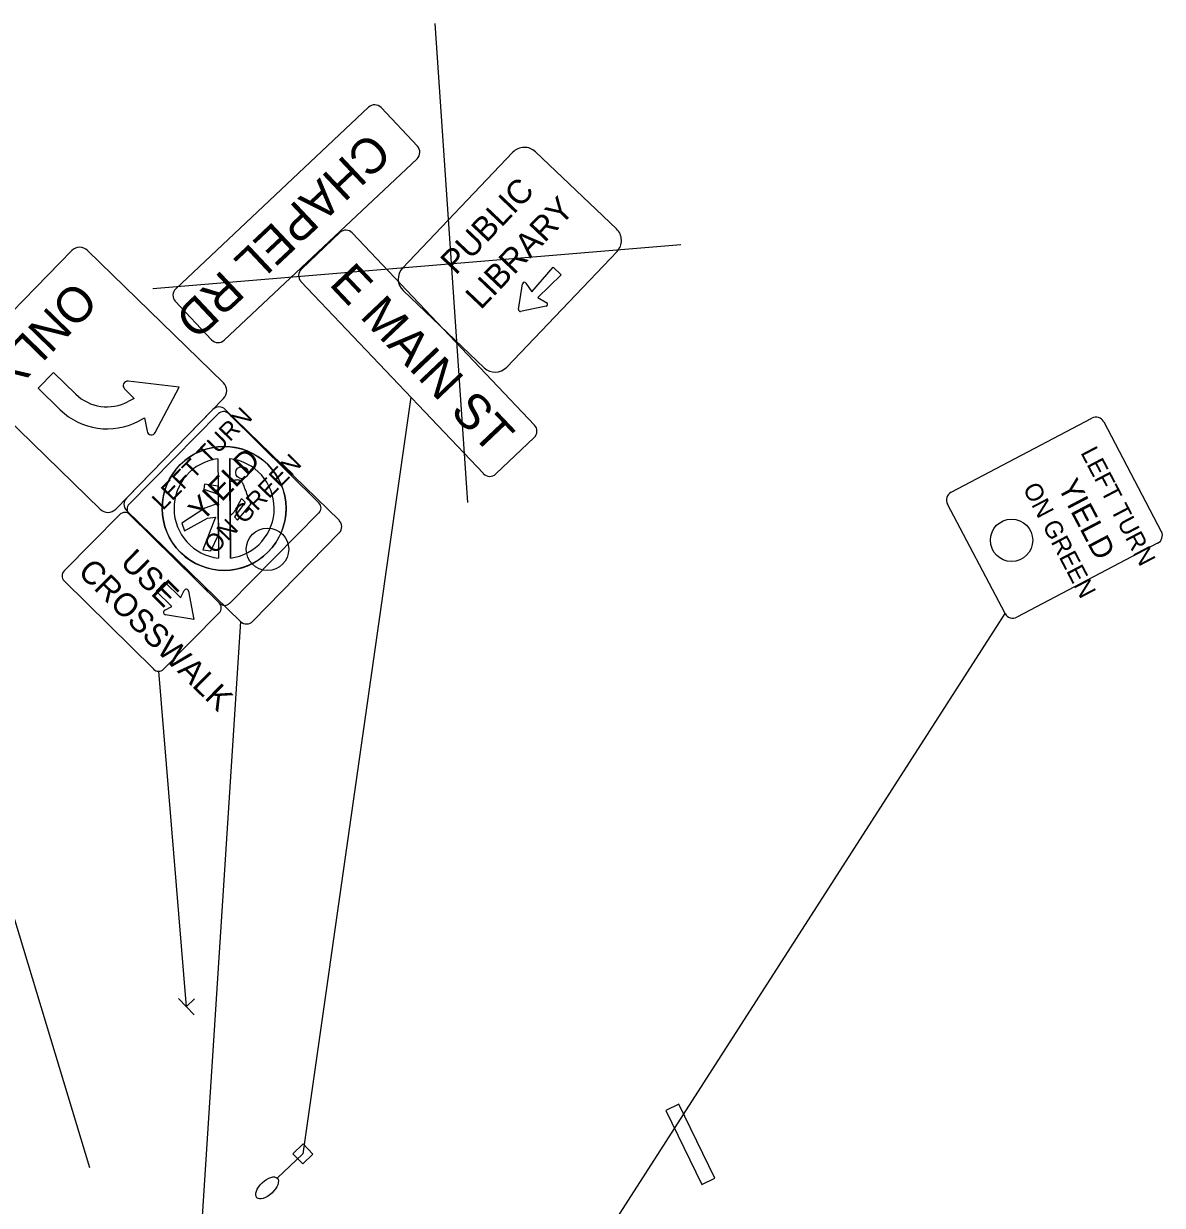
# Model space of a CAD drawing. Extents: x 1479394 to 1483660, y 379804 to 384342.
# Drawn here: x 1479604.6 to 1479765.8, y 379942.2 to 380109.6 of the extents above; entities that cross this region are included whole.
import ezdxf

# ---------------------------------------------------------------- set-up
doc = ezdxf.new("R2010")
doc.units = 0
for name, color, linetype in [('LT_X_Luminaires', 7, 'Continuous'), ('PM_P_Stop_Line', 7, 'Continuous'), ('RD_P_Text', 7, 'Continuous'), ('SC_Scratch15', 7, 'Continuous'), ('SH_Text', 7, 'Continuous')]:
    doc.layers.add(name, color=color, linetype=linetype)

msp = doc.modelspace()

# ---------------------------------------------------------------- linework, layer by layer
at = {"layer": 'LT_X_Luminaires'}
msp.add_line((1479644.13, 379949.51), (1479640.5, 379946.07), dxfattribs=at)
msp.add_lwpolyline([(1479645.54, 379949.47), (1479644.09, 379948.1), (1479642.72, 379949.55), (1479644.17, 379950.93)], close=True, dxfattribs=at)
msp.add_ellipse((1479639.05, 379944.7), major_axis=(-1.45, -1.38), ratio=0.5, dxfattribs=at)
at = {"layer": 'PM_P_Stop_Line'}
msp.add_lwpolyline([(1479697.34, 379956.57), (1479695.49, 379955.68), (1479700.59, 379945.17), (1479702.44, 379946.07)], close=True, dxfattribs=at)
at = {"layer": 'RD_P_Text'}
for p, q in [((1479662.8, 380109.55), (1479667.44, 380041.75)), ((1479697.63, 380078.23), (1479622.88, 380072.01)), ((1479633.77, 380047.96), (1479633.85, 380033.88)), ((1479630.2, 380044.34), (1479630.08, 380043.64)), ((1479630.2, 380044.34), (1479630.08, 380043.64)), ((1479632.11, 380044.08), (1479630.2, 380044.34)), ((1479632.11, 380044.08), (1479630.2, 380044.34)), ((1479633.79, 380044.65), (1479633.79, 380044.5)), ((1479633.79, 380044.5), (1479633.82, 380039.94)), ((1479630.08, 380043.64), (1479632.12, 380042.91)), ((1479630.08, 380043.64), (1479632.12, 380042.91)), ((1479632.12, 380042.91), (1479632.12, 380043.14)), ((1479635.44, 380042.34), (1479635.94, 380041.8)), ((1479635.44, 380042.34), (1479635.94, 380041.8)), ((1479630.25, 380040.94), (1479627, 380038.84)), ((1479630.25, 380040.94), (1479627, 380038.84)), ((1479631.58, 380041.43), (1479630.25, 380040.94)), ((1479631.58, 380041.43), (1479630.25, 380040.94)), ((1479632.13, 380041.61), (1479631.58, 380041.43)), ((1479632.13, 380041.61), (1479631.58, 380041.43)), ((1479632.13, 380041.52), (1479632.13, 380041.61)), ((1479632.16, 380037.16), (1479632.13, 380041.52)), ((1479635.94, 380041.8), (1479634.42, 380039.74)), ((1479635.94, 380041.8), (1479634.42, 380039.74)), ((1479634.84, 380039.26), (1479636.78, 380041.54)), ((1479634.84, 380039.26), (1479636.78, 380041.54)), ((1479636.78, 380041.54), (1479636.77, 380041.56)), ((1479636.78, 380041.54), (1479636.77, 380041.56)), ((1479627.37, 380037.75), (1479630.6, 380039.53)), ((1479627.37, 380037.75), (1479630.6, 380039.53)), ((1479631.74, 380039.67), (1479629.97, 380035.07)), ((1479631.74, 380039.67), (1479629.97, 380035.07)), ((1479630.6, 380039.53), (1479631.74, 380039.67)), ((1479630.6, 380039.53), (1479631.74, 380039.67)), ((1479634.42, 380039.74), (1479634.84, 380039.26)), ((1479634.42, 380039.74), (1479634.84, 380039.26)), ((1479627, 380038.84), (1479627.37, 380037.75)), ((1479627, 380038.84), (1479627.37, 380037.75)), ((1479631.07, 380034.93), (1479632.16, 380037.16)), ((1479631.07, 380034.93), (1479632.16, 380037.16)), ((1479629.97, 380035.07), (1479631.07, 380034.93)), ((1479629.97, 380035.07), (1479631.07, 380034.93)), ((1479623.36, 380029.2), (1479624.6, 380030.45)), ((1479624.6, 380030.45), (1479626.79, 380028.28)), ((1479626.8, 380028.27), (1479627.31, 380029.27)), ((1479627.95, 380029.18), (1479628.67, 380025.19)), ((1479626.25, 380027.57), (1479626.25, 380027.57)), ((1479626.79, 380028.28), (1479626.8, 380028.27)), ((1479624.57, 380026.5), (1479625.56, 380027.02)), ((1479628.67, 380025.19), (1479624.67, 380025.86)), ((1479623.7, 380017.86), (1479627.61, 379970.36)), ((1479628.72, 379969.21), (1479626.5, 379971.51)), ((1479627.61, 379970.36), (1479628.76, 379971.48))]:
    msp.add_line(p, q, dxfattribs=at)
for points in [[(1479632.18, 380054.33), (1479619.52, 380041.53)], [(1479646.39, 380041.69), (1479633.59, 380054.34)], [(1479632.08, 380047.95), (1479632.11, 380044.12), (1479632.12, 380043.14), (1479632.12, 380043.14)], [(1479633.79, 380044.5), (1479633.77, 380047.96)], [(1479632.12, 380043.14), (1479632.11, 380044.08), (1479632.11, 380044.08)], [(1479633.85, 380033.88), (1479633.82, 380039.47), (1479633.82, 380039.47), (1479633.82, 380039.47), (1479633.79, 380044.5), (1479633.79, 380044.5)], [(1479633.79, 380044.5), (1479633.79, 380044.5)], [(1479632.12, 380043.14), (1479632.13, 380041.52), (1479632.16, 380036.28), (1479632.18, 380033.87)], [(1479618.2, 380040.04), (1479610.32, 380032.07)], [(1479619.53, 380040.12), (1479632.34, 380027.47)], [(1479632.27, 380027.53), (1479619.6, 380040.05)], [(1479633.75, 380027.47), (1479646.4, 380040.28)], [(1479610.33, 380030.67), (1479623, 380018.15)], [(1479625.55, 380027.03), (1479623.36, 380029.2)], [(1479624.4, 380018.16), (1479632.28, 380026.13)]]:
    msp.add_lwpolyline(points, dxfattribs=at)
for centre, radius in [((1479632.97, 380040.91), 8.77), ((1479635.49, 380045.98), 0.864)]:
    msp.add_circle(centre, radius, dxfattribs=at)
for centre, radius, start, end in [((1479632.89, 380053.63), 1, 45.3424, 135.3424), ((1479632.97, 380040.91), 8.77, 315.3424, 135.3424), ((1479632.97, 380040.91), 7.09, 97.1904, 263.5904), ((1479632.97, 380040.91), 7.09, 97.1904, 263.5904), ((1479632.97, 380040.91), 7.09, 277.1615, 83.5138), ((1479632.97, 380040.91), 7.09, 277.1615, 83.5138), ((1479632.97, 380040.91), 8.77, 135.3424, 315.3424), ((1479633.99, 380042.97), 1.54, 97.4176, 97.4708), ((1479620.24, 380040.83), 1, 135.3424, 225.3424), ((1479645.69, 380040.98), 1, 315.3424, 45.3424), ((1479618.91, 380039.35), 0.989, 45.3424, 135.3424), ((1479611.02, 380031.37), 0.989, 135.3424, 225.3424), ((1479627.61, 380029.12), 0.342, 10.2632, 152.9802), ((1479631.57, 380026.83), 0.989, 315.3424, 45.3424), ((1479633.04, 380028.18), 1, 225.3424, 315.3424), ((1479624.73, 380026.2), 0.342, 117.7046, 260.4217), ((1479623.69, 380018.85), 0.989, 225.3424, 315.3424)]:
    msp.add_arc(centre, radius, start, end, dxfattribs=at)
for points in [[(1479636.77, 380041.56), (1479636.41, 380042.45), (1479635.87, 380043.88), (1479635.67, 380044.4), (1479635.57, 380044.55), (1479635.45, 380044.66), (1479635.17, 380044.95), (1479634.48, 380044.96), (1479634.06, 380044.76), (1479633.79, 380044.65)], [(1479636.77, 380041.56), (1479636.41, 380042.45), (1479635.87, 380043.88), (1479635.67, 380044.4), (1479635.57, 380044.55), (1479635.45, 380044.66), (1479635.17, 380044.95), (1479634.48, 380044.96), (1479634.06, 380044.76), (1479633.79, 380044.65)], [(1479633.82, 380039.94), (1479633.89, 380039.97), (1479634.08, 380040.07), (1479634.38, 380040.42), (1479634.61, 380040.77), (1479634.98, 380041.43), (1479635.22, 380041.89), (1479635.44, 380042.34)], [(1479633.82, 380039.94), (1479633.89, 380039.97), (1479634.08, 380040.07), (1479634.38, 380040.42), (1479634.61, 380040.77), (1479634.98, 380041.43), (1479635.22, 380041.89), (1479635.44, 380042.34)]]:
    msp.add_open_spline(points, degree=3, dxfattribs=at)
at = {"layer": 'SC_Scratch15'}
for p, q in [((1479578.23, 380065.44), (1479613.9, 379947.6)), ((1479608.83, 380060.15), (1479606.65, 380057.92)), ((1479611.96, 380057.1), (1479608.83, 380060.15)), ((1479606.65, 380057.92), (1479609.78, 380054.86)), ((1479618.87, 380057.86), (1479620.24, 380056.49)), ((1479626.61, 380058.09), (1479619.38, 380058.92)), ((1479623.23, 380051.66), (1479626.61, 380058.09)), ((1479620.24, 380056.49), (1479619.37, 380056.03)), ((1479620.83, 380053.27), (1479621.7, 380053.73)), ((1479621.7, 380053.73), (1479622.06, 380051.83)), ((1479680.54, 379927.89), (1479743.52, 380026.03)), ((1479635.28, 380024.91), (1479629.35, 379932.58))]:
    msp.add_line(p, q, dxfattribs=at)
for points in [[(1479611.41, 380077.42), (1479596.14, 380061.76)], [(1479632.86, 380058.69), (1479613.62, 380077.45)], [(1479596.17, 380059.55), (1479615.41, 380040.79)], [(1479617.62, 380040.82), (1479632.89, 380056.48)], [(1479619.15, 380042.38), (1479631.36, 380054.91)], [(1479633.13, 380054.94), (1479649.24, 380039.23)], [(1479735.9, 380043.21), (1479755.81, 380053.68)], [(1479757.5, 380053.15), (1479765.64, 380037.66)], [(1479743.52, 380026.03), (1479735.37, 380041.52)], [(1479635.28, 380024.91), (1479619.17, 380040.62)], [(1479649.26, 380037.46), (1479637.05, 380024.93)], [(1479765.12, 380035.98), (1479745.2, 380025.5)]]:
    msp.add_lwpolyline(points, dxfattribs=at)
for centre in [(1479744.44, 380036.4), (1479639.11, 380035.13)]:
    msp.add_circle(centre, 3, dxfattribs=at)
for centre, radius, start, end in [((1479612.53, 380076.33), 1.56, 45.7261, 135.7261), ((1479619.31, 380058.3), 0.625, 83.4804, 225.2521), ((1479631.77, 380057.57), 1.56, 315.7261, 45.7261), ((1479616.4, 380061.65), 6.35, 225.7261, 297.8648), ((1479616.4, 380061.65), 9.48, 225.7261, 297.8686), ((1479632.26, 380054.04), 1.25, 45.7261, 135.7261), ((1479756.39, 380052.57), 1.25, 27.7335, 117.7335), ((1479622.67, 380051.95), 0.625, 190.5197, 332.2914), ((1479620.04, 380041.51), 1.25, 135.7261, 225.7261), ((1479736.48, 380042.1), 1.25, 117.7335, 207.7335), ((1479616.5, 380041.91), 1.56, 225.7261, 315.7261), ((1479648.37, 380038.33), 1.25, 315.7261, 45.7261), ((1479764.54, 380037.08), 1.25, 297.7335, 27.7335), ((1479744.62, 380026.61), 1.25, 207.7335, 297.7335), ((1479636.15, 380025.8), 1.25, 225.7261, 315.7261)]:
    msp.add_arc(centre, radius, start, end, dxfattribs=at)
at = {"layer": 'SH_Text'}
for p, q in [((1479676.51, 380071.59), (1479679.55, 380075.07)), ((1479676.51, 380071.59), (1479679.55, 380075.07)), ((1479679.55, 380075.07), (1479680.67, 380073.99)), ((1479679.55, 380075.07), (1479680.67, 380073.99)), ((1479674.65, 380069.09), (1479675.23, 380072.73)), ((1479674.65, 380069.09), (1479675.23, 380072.73)), ((1479675.69, 380072.83), (1479676.51, 380071.59)), ((1479675.69, 380072.83), (1479676.51, 380071.59)), ((1479680.67, 380073.99), (1479677.36, 380070.79)), ((1479680.67, 380073.99), (1479677.36, 380070.79)), ((1479677.36, 380070.79), (1479678.63, 380070.03)), ((1479677.36, 380070.79), (1479678.63, 380070.03)), ((1479677.78, 380071.97), (1479677.78, 380071.97)), ((1479678.56, 380069.57), (1479674.94, 380068.81)), ((1479678.56, 380069.57), (1479674.94, 380068.81)), ((1479659.4, 380056.66), (1479644.13, 379949.51))]:
    msp.add_line(p, q, dxfattribs=at)
for points in [[(1479653.42, 380097.71), (1479626.12, 380072.01)], [(1479660.33, 380092.2), (1479655.19, 380097.66)], [(1479658.23, 380074.95), (1479673.84, 380091.35)], [(1479677.04, 380091.42), (1479688.51, 380080.5)], [(1479632.97, 380064.73), (1479660.28, 380090.43)], [(1479649.34, 380079.97), (1479643.9, 380074.81)], [(1479676.92, 380052.72), (1479651.11, 380079.92)], [(1479688.59, 380077.3), (1479672.98, 380060.91)], [(1479643.85, 380073.04), (1479669.67, 380045.84)], [(1479669.78, 380060.83), (1479658.31, 380071.75)], [(1479631.2, 380064.78), (1479626.06, 380070.24)], [(1479676.87, 380050.95), (1479671.43, 380045.79)]]:
    msp.add_lwpolyline(points, dxfattribs=at)
for centre, radius, start, end in [((1479654.28, 380096.8), 1.25, 43.2619, 133.2619), ((1479659.42, 380091.34), 1.25, 313.2619, 43.2619), ((1479675.48, 380089.78), 2.26, 46.4, 136.4), ((1479650.2, 380079.06), 1.25, 43.5, 133.5), ((1479686.95, 380078.86), 2.26, 316.4, 46.4), ((1479644.76, 380073.9), 1.25, 133.5, 223.5), ((1479659.87, 380073.39), 2.26, 136.4, 226.4), ((1479675.48, 380072.69), 0.253, 33.4238, 170.8971), ((1479675.48, 380072.69), 0.253, 33.4238, 170.8971), ((1479626.97, 380071.1), 1.25, 133.2619, 223.2619), ((1479678.5, 380069.81), 0.253, 281.9029, 59.3762), ((1479678.5, 380069.81), 0.253, 281.9029, 59.3762), ((1479674.9, 380069.05), 0.253, 172.3064, 280.4936), ((1479674.9, 380069.05), 0.253, 172.3064, 280.4936), ((1479632.11, 380065.64), 1.25, 223.2619, 313.2619), ((1479671.34, 380062.47), 2.26, 226.4, 316.4), ((1479676.01, 380051.86), 1.25, 313.5, 43.5), ((1479670.57, 380046.7), 1.25, 223.5, 313.5)]:
    msp.add_arc(centre, radius, start, end, dxfattribs=at)

# ---------------------------------------------------------------- texts
at = {"layer": 'RD_P_Text'}
for s, p in [('USE', (1479618.1, 380033.09)), ('CROSSWALK', (1479612.12, 380031.77))]:
    msp.add_text(s, height=3.296, rotation=315.3424, dxfattribs=at).set_placement(p)
at = {"layer": 'SC_Scratch15'}
for s, height, rotation, p in [('ONLY', 5, 225.7261, (1479611.83, 380073.38)), ('LEFT TURN', 2.503, 45.7261, (1479624.3, 380040.54)), ('YIELD', 3.128, 45.7261, (1479629.85, 380038.91)), ('LEFT TURN', 2.503, 297.7335, (1479754.15, 380048.82)), ('ON GREEN', 2.503, 45.7261, (1479631.64, 380034.32)), ('ON GREEN', 2.503, 297.7335, (1479745.98, 380043.76)), ('YIELD', 3.128, 297.7335, (1479750.89, 380044.04))]:
    msp.add_text(s, height=height, rotation=rotation, dxfattribs=at).set_placement(p)
at = {"layer": 'SH_Text'}
for s, height, rotation, p in [('CHAPEL RD', 5, 223.2619, (1479653.57, 380094.42)), ('PUBLIC', 3.395, 46.4, (1479665.76, 380073.84)), ('LIBRARY', 3.395, 46.4, (1479669.3, 380068.94)), ('E MAIN ST', 5, 313.5, (1479647.7, 380072.61))]:
    msp.add_text(s, height=height, rotation=rotation, dxfattribs=at).set_placement(p)

doc.saveas('drawing.dxf')
